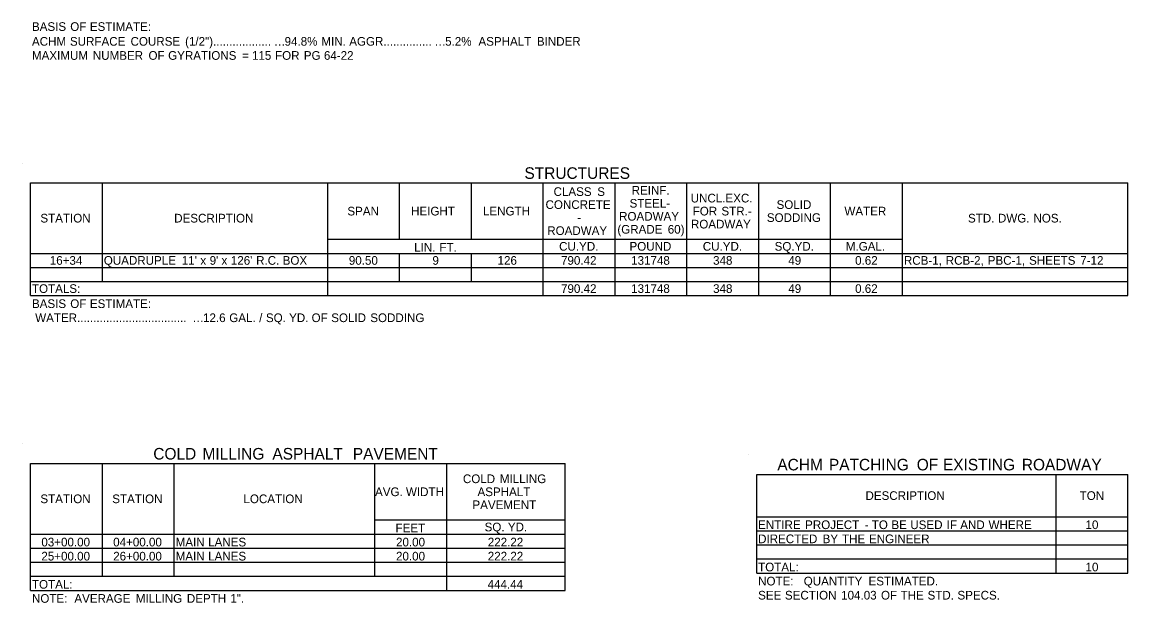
# Model space of a CAD drawing. Extents: x 1940653 to 1945779, y 534266 to 535271.
# Drawn here: x 1942440 to 1943128, y 534425 to 534786 of the extents above; entities that cross this region are included whole.
import ezdxf

# ---------------------------------------------------------------- set-up
doc = ezdxf.new("R2010")
doc.units = 0
doc.layers.add('Default', color=7, linetype='Continuous')
doc.layers.add('R_Logo', color=7, linetype='Continuous')

msp = doc.modelspace()

# ---------------------------------------------------------------- linework, layer by layer
at = {"layer": 'Default'}
for p, q in [((1942444.79, 534686.09), (1943128.37, 534686.09)), ((1942444.79, 534615.89), (1942444.79, 534686.09)), ((1942444.79, 534615.89), (1942444.79, 534686.09)), ((1942489.55, 534624.66), (1942489.55, 534686.09)), ((1942629.95, 534615.89), (1942629.95, 534686.09)), ((1942674.7, 534650.99), (1942674.7, 534686.09)), ((1942719.45, 534650.99), (1942719.45, 534686.09)), ((1942764.2, 534615.89), (1942764.2, 534686.09)), ((1942808.96, 534615.89), (1942808.96, 534686.09)), ((1942853.71, 534615.89), (1942853.71, 534686.09)), ((1942898.46, 534615.89), (1942898.46, 534686.09)), ((1942943.21, 534615.89), (1942943.21, 534686.09)), ((1942987.97, 534615.89), (1942987.97, 534686.09)), ((1943128.37, 534615.89), (1943128.37, 534686.09)), ((1942629.95, 534650.99), (1942987.97, 534650.99)), ((1942808.96, 534615.89), (1942808.96, 534650.99)), ((1942853.71, 534615.89), (1942853.71, 534650.99)), ((1942898.46, 534615.89), (1942898.46, 534650.99)), ((1942943.21, 534615.89), (1942943.21, 534650.99)), ((1942987.97, 534624.66), (1942987.97, 534650.99)), ((1942444.79, 534642.21), (1943128.37, 534642.21)), ((1942489.55, 534624.66), (1942489.55, 534642.21)), ((1942674.7, 534624.66), (1942674.7, 534642.21)), ((1942674.7, 534624.66), (1942674.7, 534642.21)), ((1942719.45, 534624.66), (1942719.45, 534642.21)), ((1942719.45, 534624.66), (1942719.45, 534642.21)), ((1942764.2, 534624.66), (1942764.2, 534642.21)), ((1942987.97, 534642.21), (1943128.37, 534642.21)), ((1943128.37, 534615.89), (1943128.37, 534642.21)), ((1942444.79, 534633.44), (1943128.37, 534633.44)), ((1942444.79, 534624.66), (1942764.2, 534624.66)), ((1942489.55, 534624.66), (1942629.95, 534624.66)), ((1942629.95, 534624.66), (1942987.97, 534624.66)), ((1942629.95, 534615.89), (1942629.95, 534624.66)), ((1942943.21, 534624.66), (1942987.97, 534624.66)), ((1942987.97, 534624.66), (1943128.37, 534624.66)), ((1942444.79, 534615.89), (1943128.37, 534615.89)), ((1942444.79, 534511.27), (1942777.81, 534511.27)), ((1942444.79, 534432.3), (1942444.79, 534511.27)), ((1942444.79, 534432.3), (1942444.79, 534511.27)), ((1942489.55, 534441.07), (1942489.55, 534511.27)), ((1942534.3, 534441.07), (1942534.3, 534511.27)), ((1942659.34, 534441.07), (1942659.34, 534511.27)), ((1942704.1, 534432.3), (1942704.1, 534511.27)), ((1942777.81, 534432.3), (1942777.81, 534511.27)), ((1942777.81, 534432.3), (1942777.81, 534511.27)), ((1942897.15, 534504.51), (1943128.37, 534504.51)), ((1942897.15, 534443.08), (1942897.15, 534504.51)), ((1942897.15, 534443.08), (1942897.15, 534504.51)), ((1943083.61, 534443.08), (1943083.61, 534504.51)), ((1943128.37, 534443.08), (1943128.37, 534504.51)), ((1942659.34, 534476.17), (1942777.81, 534476.17)), ((1942659.34, 534441.07), (1942659.34, 534476.17)), ((1942897.15, 534478.18), (1943128.37, 534478.18)), ((1943083.61, 534443.08), (1943083.61, 534478.18)), ((1943128.37, 534443.08), (1943128.37, 534478.18)), ((1942897.15, 534469.41), (1943128.37, 534469.41)), ((1942444.79, 534467.4), (1942777.81, 534467.4)), ((1942489.55, 534441.07), (1942489.55, 534467.4)), ((1942534.3, 534441.07), (1942534.3, 534467.4)), ((1942704.1, 534441.07), (1942704.1, 534467.4)), ((1942444.79, 534458.62), (1942777.81, 534458.62)), ((1942897.15, 534460.63), (1943128.37, 534460.63)), ((1942444.79, 534449.85), (1942777.81, 534449.85)), ((1942897.15, 534451.86), (1943128.37, 534451.86)), ((1942897.15, 534443.08), (1943128.37, 534443.08)), ((1942444.79, 534441.07), (1942489.55, 534441.07)), ((1942444.79, 534441.07), (1942777.81, 534441.07)), ((1942489.55, 534441.07), (1942534.3, 534441.07)), ((1942534.3, 534441.07), (1942659.34, 534441.07)), ((1942704.1, 534441.07), (1942777.81, 534441.07)), ((1942444.79, 534432.3), (1942777.81, 534432.3))]:
    msp.add_line(p, q, dxfattribs=at)
at = {"layer": 'R_Logo'}
for p, q in [((1942439.53, 534698.37), (1942439.53, 534698.37)), ((1942439.53, 534523.56), (1942439.53, 534523.56)), ((1942891.88, 534516.79), (1942891.88, 534516.79))]:
    msp.add_line(p, q, dxfattribs=at)

# ---------------------------------------------------------------- texts
at = {"layer": 'Default'}
for s, height, p in [('BASIS', 5.4, (1942445.67, 534780.78)), (' OF', 5.4, (1942467.51, 534780.78)), (' ESTIMATE:', 5.4, (1942479.73, 534780.78)), ('ACHM', 5.4, (1942445.67, 534771.57)), (' SURFACE', 5.4, (1942467.32, 534771.57)), (' COURSE', 5.4, (1942505.07, 534771.57)), (' (1/2")..................', 5.4, (1942539.05, 534771.57)), ('…', 5.4, (1942596.38, 534771.57)), ('94.8%', 5.4, (1942603.04, 534771.57)), (' MIN.', 5.4, (1942623.95, 534771.57)), (' AGGR...............', 5.4, (1942641.31, 534771.57)), ('…', 5.4, (1942696.4, 534771.57)), ('5.2%', 5.4, (1942703.06, 534771.57)), ('  ASPHALT', 5.4, (1942719.78, 534771.57)), (' BINDER', 5.4, (1942758.2, 534771.57)), ('MAXIMUM', 5.4, (1942445.67, 534762.79)), (' NUMBER', 5.4, (1942481.57, 534762.79)), (' OF', 5.4, (1942516.26, 534762.79)), (' GYRATIONS', 5.4, (1942528.49, 534762.79)), (' =', 5.4, (1942574.63, 534762.79)), (' 115', 5.4, (1942580.71, 534762.79)), (' FOR', 5.4, (1942595.09, 534762.79)), (' PG', 5.4, (1942613.01, 534762.79)), (' 64-22', 5.4, (1942625.53, 534762.79)), ('STRUCTURES', 7.2, (1942752.45, 534688.63)), ('CLASS', 5.4, (1942770.6, 534677.99)), (' S', 5.4, (1942795.8, 534677.99)), ('REINF.', 5.4, (1942819.23, 534678.8)), ('STEEL-', 5.4, (1942817.94, 534670.7)), ('UNCL.EXC.', 5.4, (1942856.01, 534673.94)), ('SPAN', 5.4, (1942642.14, 534665.84)), ('HEIGHT', 5.4, (1942681.85, 534665.84)), ('LENGTH', 5.4, (1942726.61, 534665.84)), ('CONCRETE', 5.4, (1942765.6, 534669.89)), ('FOR', 5.4, (1942857.27, 534665.84)), (' STR.-', 5.4, (1942873.16, 534665.84)), ('SOLID', 5.4, (1942909.5, 534669.89)), ('WATER', 5.4, (1942951.78, 534665.84)), ('STATION', 5.4, (1942450.91, 534661.45)), ('DESCRIPTION', 5.4, (1942534.27, 534661.45)), ('-', 5.4, (1942785.35, 534661.79)), ('ROADWAY', 5.4, (1942811.42, 534662.6)), ('ROADWAY', 5.4, (1942856.17, 534657.74)), ('SODDING', 5.4, (1942903.46, 534661.79)), ('STD.', 5.4, (1943028.76, 534661.45)), (' DWG.', 5.4, (1943045.43, 534661.45)), (' NOS.', 5.4, (1943067.54, 534661.45)), ('ROADWAY', 5.4, (1942766.66, 534653.69)), ('(GRADE', 5.4, (1942810.34, 534654.5)), (' 60)', 5.4, (1942839.73, 534654.5)), ('LIN.', 5.4, (1942683.76, 534643.29)), (' FT.', 5.4, (1942697.5, 534643.29)), ('CU.YD.', 5.4, (1942774.05, 534643.9)), ('POUND', 5.4, (1942817.89, 534643.9)), ('CU.YD.', 5.4, (1942863.56, 534643.9)), ('SQ.YD.', 5.4, (1942908.31, 534643.9)), ('M.GAL.', 5.4, (1942952.65, 534643.9)), ('16+34', 5.4, (1942456.76, 534635.13)), ('QUADRUPLE', 5.4, (1942490.42, 534635.13)), (" 11'", 5.4, (1942536.98, 534635.13)), (' x', 5.4, (1942548.55, 534635.13)), (" 9'", 5.4, (1942554.36, 534635.13)), (' x', 5.4, (1942561.74, 534635.13)), (" 126'", 5.4, (1942567.55, 534635.13)), (' R.C.', 5.4, (1942583.31, 534635.13)), (' BOX', 5.4, (1942599.84, 534635.13)), ('90.50', 5.4, (1942643.07, 534635.13)), ('9', 5.4, (1942695.14, 534635.13)), ('126', 5.4, (1942735.71, 534635.13)), ('790.42', 5.4, (1942775.25, 534635.13)), ('131748', 5.4, (1942818.92, 534635.13)), ('348', 5.4, (1942869.96, 534635.13)), ('49', 5.4, (1942916.81, 534635.13)), ('0.62', 5.4, (1942958.45, 534635.13)), ('RCB-1,', 5.4, (1942988.84, 534635.13)), (' RCB-2,', 5.4, (1943012.91, 534635.13)), (' PBC-1,', 5.4, (1943039.06, 534635.13)), (' SHEETS', 5.4, (1943064.8, 534635.13)), (' 7-12', 5.4, (1943096.7, 534635.13)), ('TOTALS:', 5.4, (1942445.67, 534617.58)), ('790.42', 5.4, (1942775.24, 534617.58)), ('131748', 5.4, (1942818.92, 534617.58)), ('348', 5.4, (1942869.96, 534617.58)), ('49', 5.4, (1942916.82, 534617.58)), ('0.62', 5.4, (1942958.44, 534617.58)), ('BASIS', 5.4, (1942445.67, 534608.19)), (' OF', 5.4, (1942467.51, 534608.19)), (' ESTIMATE:', 5.4, (1942479.73, 534608.19)), (' WATER..................................', 5.4, (1942445.67, 534599.42)), ('…', 5.4, (1942545.58, 534599.42)), ('12.6', 5.4, (1942552.24, 534599.42)), (' GAL.', 5.4, (1942566.58, 534599.42)), (' /', 5.4, (1942585.21, 534599.42)), (' SQ.', 5.4, (1942589.4, 534599.42)), (' YD.', 5.4, (1942603.84, 534599.42)), (' OF', 5.4, (1942617.85, 534599.42)), (' SOLID', 5.4, (1942630.08, 534599.42)), (' SODDING', 5.4, (1942654.41, 534599.42)), ('COLD', 7.2, (1942521.24, 534513.82)), (' MILLING', 7.2, (1942549.24, 534513.82)), (' ASPHALT', 7.2, (1942592.78, 534513.82)), (' PAVEMENT', 7.2, (1942642.87, 534513.82)), ('ACHM', 7.2, (1942909.99, 534507.05)), (' PATCHING', 7.2, (1942939.45, 534507.05)), (' OF', 7.2, (1942994.17, 534507.05)), (' EXISTING', 7.2, (1943010.47, 534507.05)), (' ROADWAY', 7.2, (1943059.62, 534507.05)), ('COLD', 5.4, (1942714.12, 534499.12)), (' MILLING', 5.4, (1942735.13, 534499.12)), ('STATION', 5.4, (1942450.91, 534486.64)), ('STATION', 5.4, (1942495.67, 534486.64)), ('LOCATION', 5.4, (1942577.42, 534486.64)), ('AVG. WIDTH', 5.4, (1942659.38, 534491.02)), ('ASPHALT', 5.4, (1942723.21, 534491.02)), ('DESCRIPTION', 5.4, (1942964.9, 534488.65)), ('TON', 5.4, (1943098.33, 534488.65)), ('PAVEMENT', 5.4, (1942720.06, 534482.92)), (' PROJECT', 5.4, (1942925.29, 534470.49)), (' TO', 5.4, (1942966.82, 534470.49)), (' USED', 5.4, (1942990.82, 534470.49)), ('10', 5.4, (1943101.98, 534470.49)), ('FEET', 5.4, (1942672.15, 534468.48)), ('SQ.', 5.4, (1942727.63, 534469.09)), (' YD.', 5.4, (1942740.11, 534469.09)), ('ENTIRE', 5.4, (1942898.02, 534470.49)), (' -', 5.4, (1942962.45, 534470.49)), (' BE', 5.4, (1942979.06, 534470.49)), (' IF', 5.4, (1943013.48, 534470.49)), (' AND', 5.4, (1943021.93, 534470.49)), (' WHERE', 5.4, (1943039.55, 534470.49)), ('03+00.00', 5.4, (1942451.52, 534459.7)), ('04+00.00', 5.4, (1942496.27, 534459.7)), ('MAIN', 5.4, (1942535.18, 534459.7)), (' LANES', 5.4, (1942553.42, 534459.7)), ('20.00', 5.4, (1942672.46, 534459.7)), ('222.22', 5.4, (1942729.62, 534459.7)), ('DIRECTED', 5.4, (1942898.02, 534461.71)), (' BY', 5.4, (1942936.19, 534461.71)), (' THE', 5.4, (1942948.29, 534461.71)), (' ENGINEER', 5.4, (1942965.08, 534461.71)), ('25+00.00', 5.4, (1942451.52, 534450.93)), ('26+00.00', 5.4, (1942496.27, 534450.93)), ('MAIN', 5.4, (1942535.18, 534450.93)), (' LANES', 5.4, (1942553.42, 534450.93)), ('20.00', 5.4, (1942672.46, 534450.93)), ('222.22', 5.4, (1942729.62, 534450.93)), ('TOTAL:', 5.4, (1942898.02, 534444.16)), ('10', 5.4, (1943101.98, 534444.16)), ('TOTAL:', 5.4, (1942445.67, 534433.38)), ('444.44', 5.4, (1942729.5, 534433.38)), ('NOTE:', 5.4, (1942898.02, 534435.39)), ('   QUANTITY', 5.4, (1942920.42, 534435.39)), (' ESTIMATED.', 5.4, (1942964.8, 534435.39)), ('NOTE:', 5.4, (1942445.67, 534424.6)), ('  AVERAGE', 5.4, (1942468.07, 534424.6)), (' MILLING', 5.4, (1942508.34, 534424.6)), (' DEPTH', 5.4, (1942540.15, 534424.6)), (' 1".', 5.4, (1942567.21, 534424.6)), ('SEE', 5.4, (1942898.02, 534426.61)), (' SECTION', 5.4, (1942912.72, 534426.61)), (' 104.03', 5.4, (1942947.74, 534426.61)), (' OF', 5.4, (1942972.56, 534426.61)), (' THE', 5.4, (1942984.78, 534426.61)), (' STD.', 5.4, (1943001.57, 534426.61)), (' SPECS.', 5.4, (1943020.19, 534426.61))]:
    msp.add_text(s, height=height, dxfattribs=at).set_placement(p)

doc.saveas('drawing.dxf')
